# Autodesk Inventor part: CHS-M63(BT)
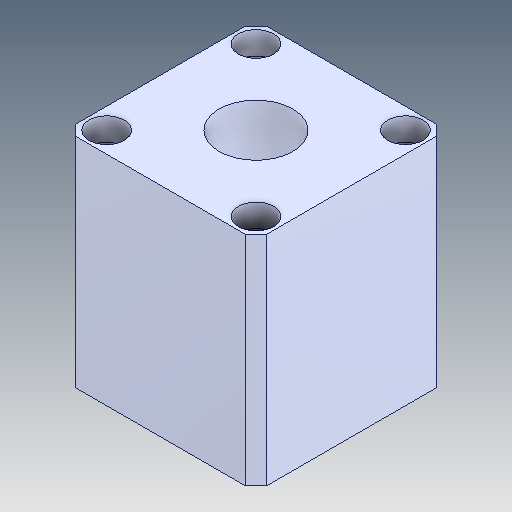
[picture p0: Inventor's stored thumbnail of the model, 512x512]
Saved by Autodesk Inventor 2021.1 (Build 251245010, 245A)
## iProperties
Created: 2021-05
Part Number: CHS-M63(BT)
Material: Ogólny
Document SubType Name: Modeling
Designer: user
Density: 1 g/cm^3
Appearance: Domyślna
Author: user
Revision Number: ÈÎºÎ
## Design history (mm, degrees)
feature "ÇÐ³ý-À­Éì3"
node "Bryła1"
